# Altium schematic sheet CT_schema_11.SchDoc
size 741 x 377 mm
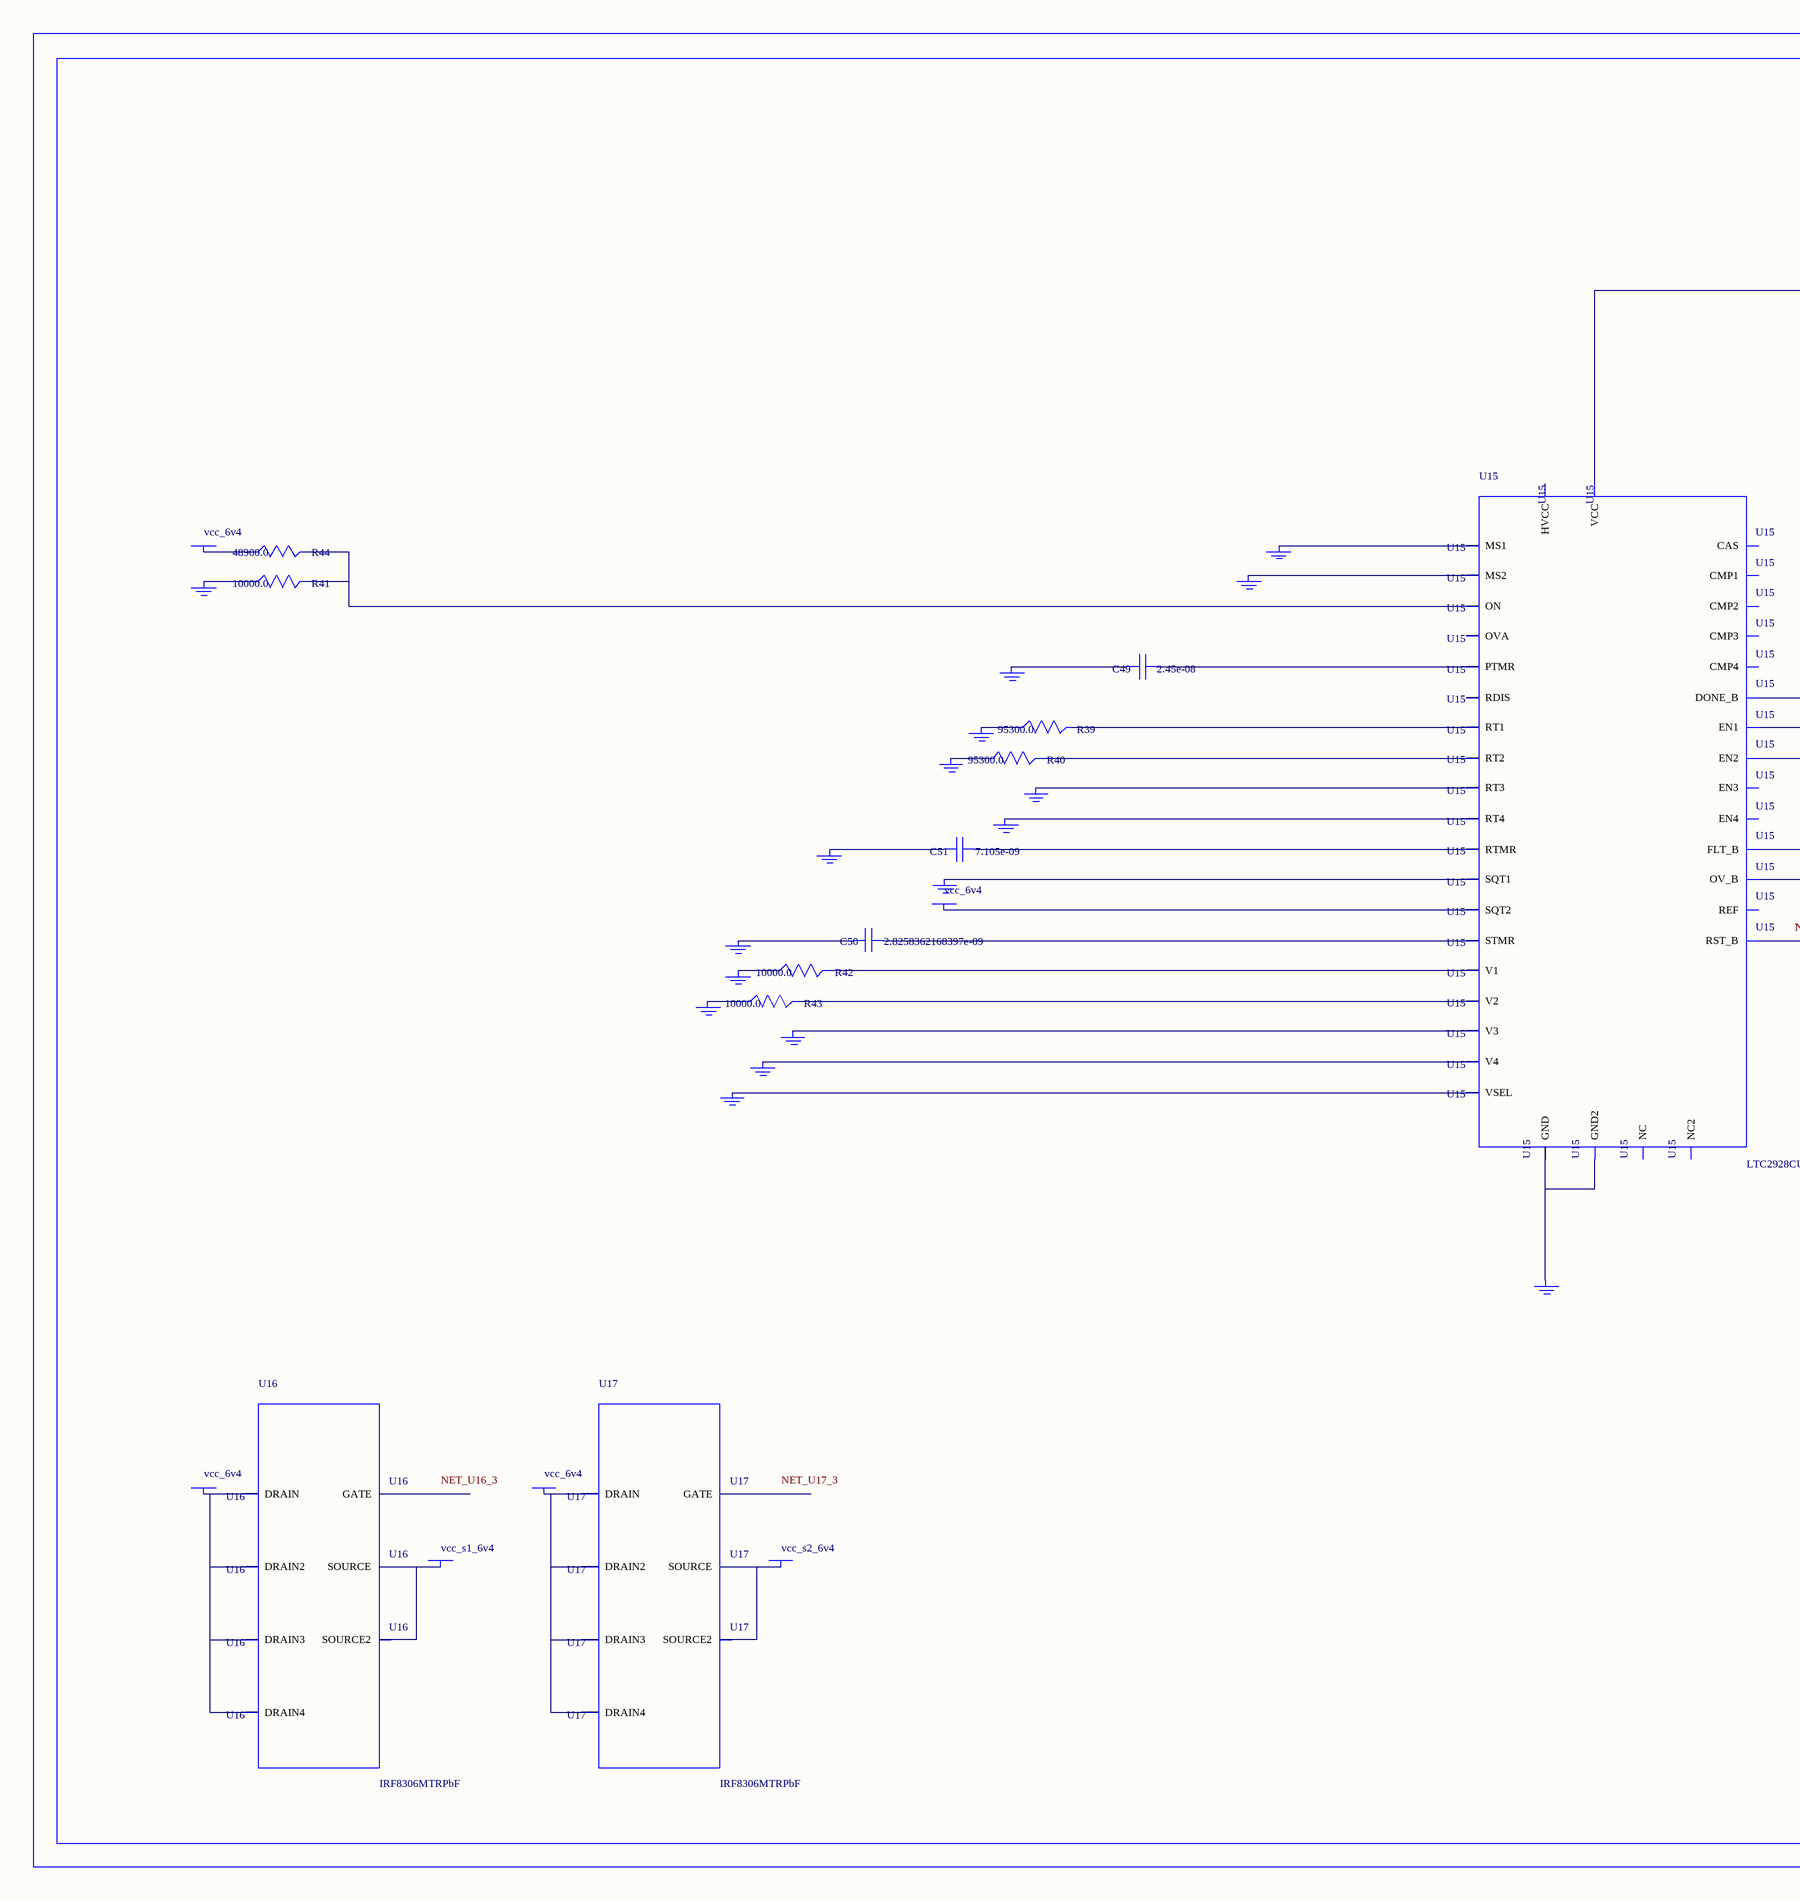
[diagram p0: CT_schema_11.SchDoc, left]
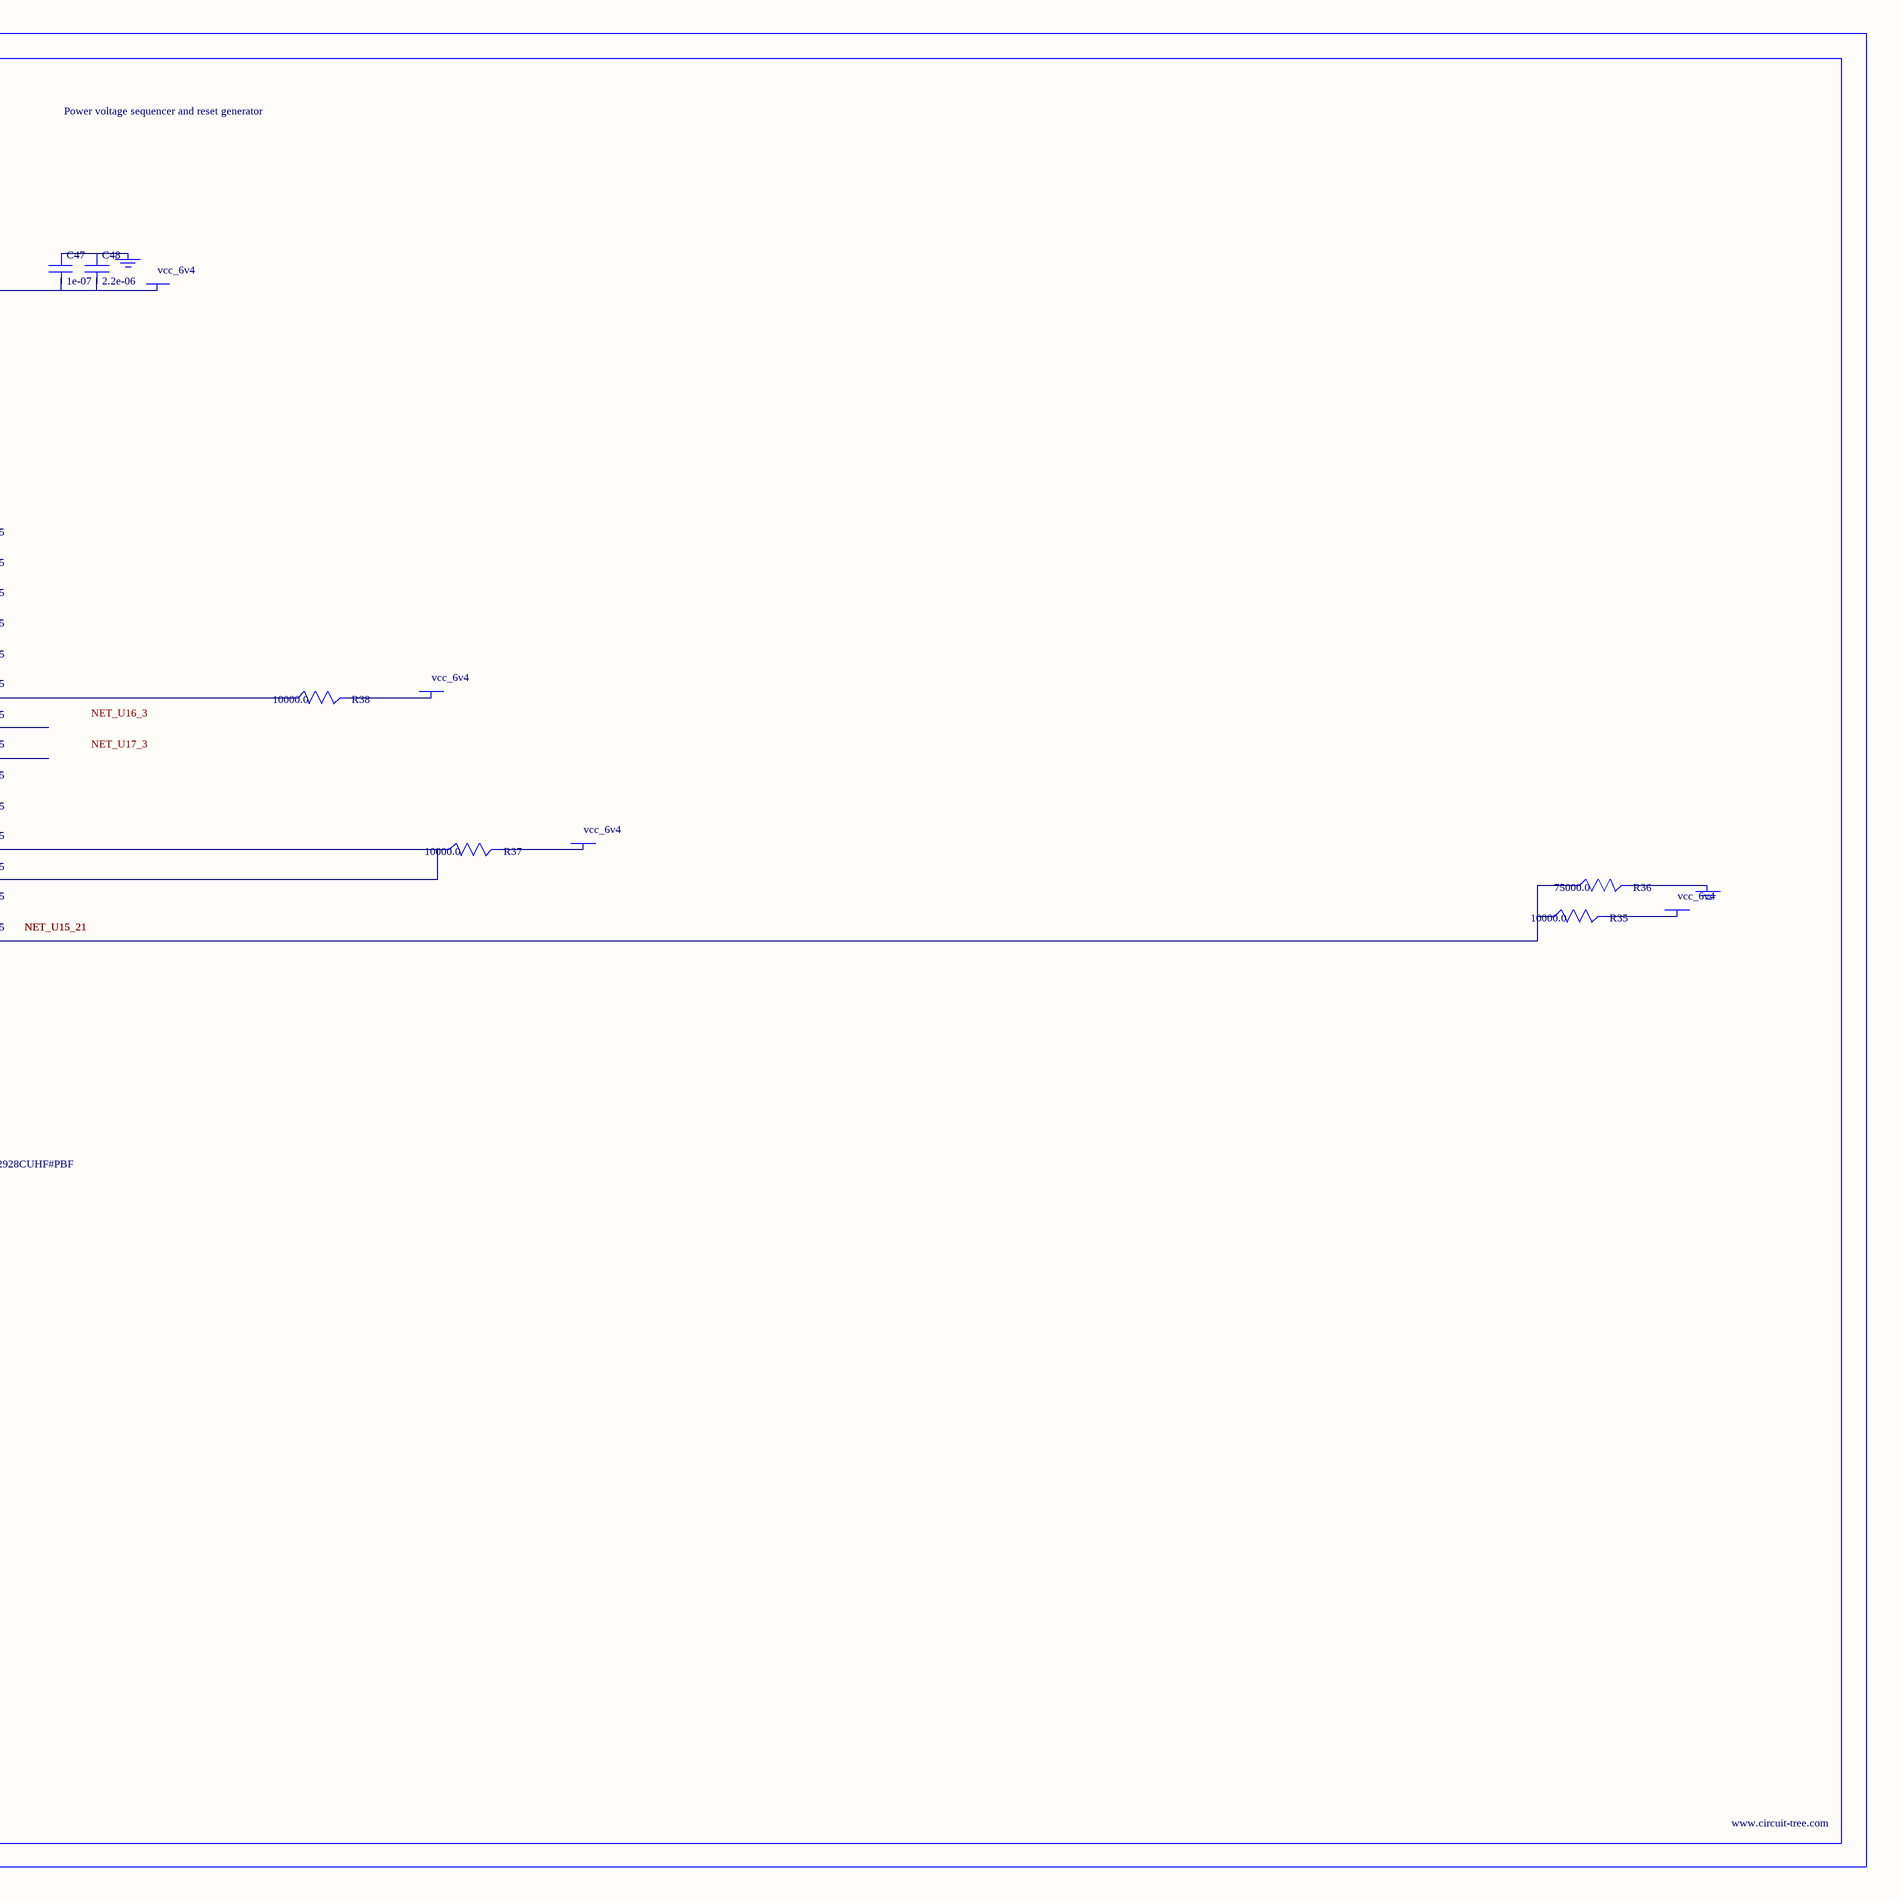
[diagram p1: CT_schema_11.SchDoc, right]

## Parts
BORDER10  (no value)
C47  1e-07  [C0402]
C48  2.2e-06  [C0603]
C49  2.45e-08  [R0603]
C50  2.8258362168397e-09  [R0603]
C51  7.105e-09  [R0603]
GND_INSTANCE_10_0  (no value)
GND_INSTANCE_10_1  (no value)
GND_INSTANCE_10_2  (no value)
GND_INSTANCE_10_3  (no value)
GND_INSTANCE_10_4  (no value)
GND_INSTANCE_10_5  (no value)
GND_INSTANCE_10_6  (no value)
GND_INSTANCE_10_7  (no value)
GND_INSTANCE_10_8  (no value)
GND_INSTANCE_10_9  (no value)
GND_INSTANCE_10_10  (no value)
GND_INSTANCE_10_11  (no value)
GND_INSTANCE_10_12  (no value)
GND_INSTANCE_10_13  (no value)
GND_INSTANCE_10_14  (no value)
GND_INSTANCE_10_15  (no value)
GND_INSTANCE_10_16  (no value)
GND_INSTANCE_10_17  (no value)
GND_INSTANCE_10_18  (no value)
POWER_INSTANCE_10_0  vcc_6v4
POWER_INSTANCE_10_1  vcc_6v4
POWER_INSTANCE_10_2  vcc_6v4
POWER_INSTANCE_10_3  vcc_6v4
POWER_INSTANCE_10_4  vcc_6v4
POWER_INSTANCE_10_5  vcc_6v4
POWER_INSTANCE_10_6  vcc_6v4
POWER_INSTANCE_10_7  vcc_s1_6v4
POWER_INSTANCE_10_8  vcc_6v4
POWER_INSTANCE_10_9  vcc_s2_6v4
R35  10000.0  [R0603]
R36  75000.0  [R0603]
R37  10000.0  [R0603]
R38  10000.0  [R0603]
R39  95300.0  [R0603]
R40  95300.0  [R0603]
R41  10000.0  [R0603]
R42  10000.0  [R0603]
R43  10000.0  [R0603]
R44  48900.0  [R0603]
U15  LTC2928CUHF#PBF  [QFN-38_UHF]
U16  IRF8306MTRPbF  [IRF8306MTRPBF]
U17  IRF8306MTRPbF  [IRF8306MTRPBF]

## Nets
NetC47_1: C47.1 C48.1 GND_INSTANCE_10_10.0(GND)
NetC47_2: C47.2 C48.2 POWER_INSTANCE_10_5.0(PWR) U15.22(VCC)
NetC49_1: C49.1 U15.27(PTMR)
NetC49_2: C49.2 GND_INSTANCE_10_13.0(GND)
NetC50_1: C50.1 U15.26(STMR)
NetC50_2: C50.2 GND_INSTANCE_10_12.0(GND)
NetC51_1: C51.1 U15.28(RTMR)
NetC51_2: C51.2 GND_INSTANCE_10_14.0(GND)
NetGND_INSTANCE_10_0_0: GND_INSTANCE_10_0.0(GND) R42.1
NetGND_INSTANCE_10_1_0: GND_INSTANCE_10_1.0(GND) R39.1
NetGND_INSTANCE_10_2_0: GND_INSTANCE_10_2.0(GND) R40.1
NetGND_INSTANCE_10_3_0: GND_INSTANCE_10_3.0(GND) U15.8(RT3)
NetGND_INSTANCE_10_4_0: GND_INSTANCE_10_4.0(GND) U15.9(RT4)
NetGND_INSTANCE_10_5_0: GND_INSTANCE_10_5.0(GND) U15.10(SQT1)
NetGND_INSTANCE_10_6_0: GND_INSTANCE_10_6.0(GND) U15.12(MS1)
NetGND_INSTANCE_10_7_0: GND_INSTANCE_10_7.0(GND) U15.13(MS2)
NetGND_INSTANCE_10_8_0: GND_INSTANCE_10_8.0(GND) R41.1
NetGND_INSTANCE_10_9_0: GND_INSTANCE_10_9.0(GND) R36.2
NetGND_INSTANCE_10_11_0: GND_INSTANCE_10_11.0(GND) U15.25(VSEL)
NetGND_INSTANCE_10_15_0: GND_INSTANCE_10_15.0(GND) U15.30(V4)
NetGND_INSTANCE_10_16_0: GND_INSTANCE_10_16.0(GND) U15.32(V3)
NetGND_INSTANCE_10_17_0: GND_INSTANCE_10_17.0(GND) R43.1
NetGND_INSTANCE_10_18_0: GND_INSTANCE_10_18.0(GND) U15.24(GND) U15.39(GND2)
NetPOWER_INSTANCE_10_0_0: POWER_INSTANCE_10_0.0(PWR) U15.11(SQT2)
NetPOWER_INSTANCE_10_1_0: POWER_INSTANCE_10_1.0(PWR) R44.1
NetPOWER_INSTANCE_10_2_0: POWER_INSTANCE_10_2.0(PWR) R38.2
NetPOWER_INSTANCE_10_3_0: POWER_INSTANCE_10_3.0(PWR) R37.2
NetPOWER_INSTANCE_10_4_0: POWER_INSTANCE_10_4.0(PWR) R35.2
NetPOWER_INSTANCE_10_6_0: POWER_INSTANCE_10_6.0(PWR) U16.1(DRAIN) U16.2(DRAIN2) U16.6(DRAIN3) U16.7(DRAIN4)
NetPOWER_INSTANCE_10_7_0: POWER_INSTANCE_10_7.0(PWR) U16.4(SOURCE) U16.5(SOURCE2)
NetPOWER_INSTANCE_10_8_0: POWER_INSTANCE_10_8.0(PWR) U17.1(DRAIN) U17.2(DRAIN2) U17.6(DRAIN3) U17.7(DRAIN4)
NetPOWER_INSTANCE_10_9_0: POWER_INSTANCE_10_9.0(PWR) U17.4(SOURCE) U17.5(SOURCE2)
NetR35_1: R35.1 R36.1 U15.21(RST_B)
NetR37_1: R37.1 U15.19(FLT_B) U15.20(OV_B)
NetR38_1: R38.1 U15.18(DONE_B)
NetR39_2: R39.2 U15.6(RT1)
NetR40_2: R40.2 U15.7(RT2)
NetR41_2: R41.2 R44.2 U15.16(ON)
NetR42_2: R42.2 U15.3(V1)
NetR43_2: R43.2 U15.38(V2)

Not connected (* = marked no-connect by the designer): U15 1(OVA) 2(EN1) 4(NC) 5(REF) 14(RDIS) 15(CAS) 17(NC2) 23(HVCC) 29(EN4) 31(EN3) 33(CMP3) 34(CMP4) 35(CMP1) 36(CMP2) 37(EN2); U16 3(GATE); U17 3(GATE)

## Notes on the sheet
- Labels drawn without touching a wire or pin: NET_U16_3, NET_U17_3

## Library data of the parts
BORDER10 = BORDER_PAGE10
C47 = C0402C104K3RACTU
C48 = GRM188R61H225KE1115D
C49 = C49
C50 = C50
C51 = C51
GND_INSTANCE_10_0-GND_INSTANCE_10_18 = GND
POWER_INSTANCE_10_0-POWER_INSTANCE_10_9 = PWR
R35 R37 R38 R41-R43 = RC0603JR-0710KL
R36 = RC0603JR-0775KL
R39 R40 = RC0603FR-0795K3L
R44 = RT0603BRD0745K9L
